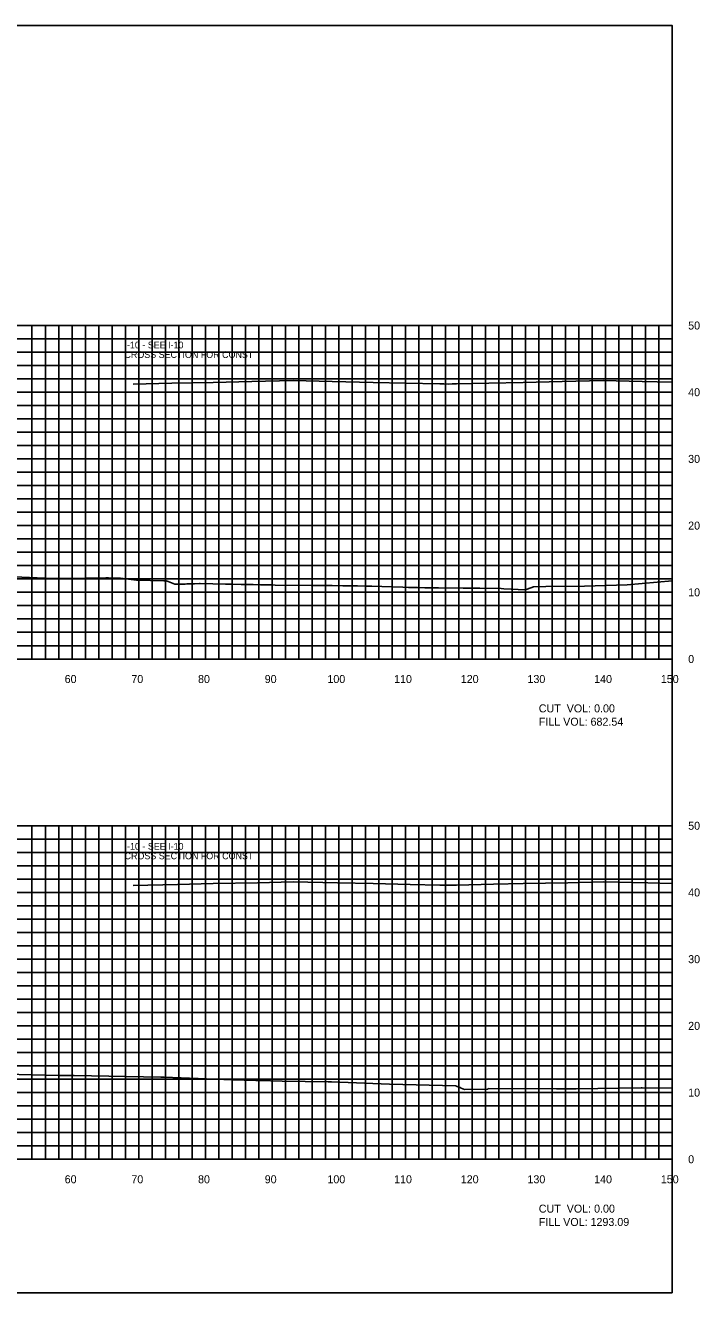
# Model space of a CAD drawing. Extents: x 1797714 to 1804825, y 249015 to 250269.
# Drawn here: x 1803024 to 1803125.1, y 250079.4 to 250269.4 of the extents above; entities that cross this region are included whole.
import ezdxf

# ---------------------------------------------------------------- set-up
doc = ezdxf.new("R2010")
doc.units = 0
for name, color, linetype in [('10', 7, 'Continuous'), ('3', 7, 'Continuous'), ('31', 7, 'Continuous'), ('60', 7, 'Continuous'), ('ANNO-TXT', 7, 'Continuous'), ('CL-CNST', 7, 'Continuous'), ('Level 62', 7, 'Continuous'), ('M-ROADS', 7, 'Continuous')]:
    doc.layers.add(name, color=color, linetype=linetype)

msp = doc.modelspace()

# ---------------------------------------------------------------- linework, layer by layer
msp.add_lwpolyline([(1802821, 250079.43), (1803121, 250079.43), (1803121, 250269.43), (1802821, 250269.43)], close=True)
at = {"layer": '60'}
for p, q in [((1803121, 250174.43), (1803121, 250224.43)), ((1803121.06, 250224.43), (1803121, 250224.43)), ((1803121.06, 250214.43), (1803121, 250214.43)), ((1803121.06, 250204.43), (1803121, 250204.43)), ((1803121.06, 250194.43), (1803121, 250194.43)), ((1803121.06, 250184.43), (1803121, 250184.43)), ((1802821, 250174.43), (1803121, 250174.43)), ((1803031, 250174.37), (1803031, 250174.43)), ((1803041, 250174.37), (1803041, 250174.43)), ((1803051, 250174.37), (1803051, 250174.43)), ((1803061, 250174.37), (1803061, 250174.43)), ((1803071, 250174.37), (1803071, 250174.43)), ((1803081, 250174.37), (1803081, 250174.43)), ((1803091, 250174.37), (1803091, 250174.43)), ((1803101, 250174.37), (1803101, 250174.43)), ((1803111, 250174.37), (1803111, 250174.43)), ((1803121, 250174.37), (1803121, 250174.43)), ((1803121.06, 250174.43), (1803121, 250174.43)), ((1803121, 250099.43), (1803121, 250149.43)), ((1803121.06, 250149.43), (1803121, 250149.43)), ((1803121.06, 250139.43), (1803121, 250139.43)), ((1803121.06, 250129.43), (1803121, 250129.43)), ((1803121.06, 250119.43), (1803121, 250119.43)), ((1803121.06, 250109.43), (1803121, 250109.43)), ((1802821, 250099.43), (1803121, 250099.43)), ((1803031, 250099.37), (1803031, 250099.43)), ((1803041, 250099.37), (1803041, 250099.43)), ((1803051, 250099.37), (1803051, 250099.43)), ((1803061, 250099.37), (1803061, 250099.43)), ((1803071, 250099.37), (1803071, 250099.43)), ((1803081, 250099.37), (1803081, 250099.43)), ((1803091, 250099.37), (1803091, 250099.43)), ((1803101, 250099.37), (1803101, 250099.43)), ((1803111, 250099.37), (1803111, 250099.43)), ((1803121, 250099.37), (1803121, 250099.43)), ((1803121.06, 250099.43), (1803121, 250099.43))]:
    msp.add_line(p, q, dxfattribs=at)
at = {"layer": 'CL-CNST'}
for points in [[(1803040.16, 250215.64), (1803045.99, 250215.77), (1803052.16, 250215.91), (1803057.99, 250216.04), (1803064.16, 250216.17), (1803069.99, 250216.04), (1803076.16, 250215.91), (1803081.02, 250215.8), (1803086.16, 250215.69), (1803086.77, 250215.68), (1803087.41, 250215.66), (1803087.41, 250215.66), (1803087.41, 250215.66), (1803088.02, 250215.67), (1803088.66, 250215.69), (1803093.52, 250215.8), (1803098.66, 250215.91), (1803104.5, 250216.04), (1803110.66, 250216.17), (1803116.5, 250216.04), (1803121, 250215.94)], [(1803040.17, 250140.48), (1803046.83, 250140.63), (1803052.17, 250140.75), (1803058.83, 250140.89), (1803064.17, 250141.01), (1803070.83, 250140.87), (1803076.17, 250140.75), (1803081.72, 250140.63), (1803086.17, 250140.53), (1803086.87, 250140.51), (1803087.42, 250140.5), (1803087.42, 250140.5), (1803087.42, 250140.5), (1803088.12, 250140.52), (1803088.67, 250140.53), (1803094.23, 250140.65), (1803098.67, 250140.75), (1803105.34, 250140.89), (1803110.67, 250141.01), (1803117.34, 250140.86), (1803121, 250140.78)]]:
    msp.add_lwpolyline(points, dxfattribs=at)
at = {"layer": 'Level 62'}
for p, q in [((1802821, 250224.43), (1803121, 250224.43)), ((1803025, 250174.43), (1803025, 250224.43)), ((1803027, 250174.43), (1803027, 250224.43)), ((1803029, 250174.43), (1803029, 250224.43)), ((1803031, 250174.43), (1803031, 250224.43)), ((1803033, 250174.43), (1803033, 250224.43)), ((1803035, 250174.43), (1803035, 250224.43)), ((1803037, 250174.43), (1803037, 250224.43)), ((1803039, 250174.43), (1803039, 250224.43)), ((1803041, 250174.43), (1803041, 250224.43)), ((1803043, 250174.43), (1803043, 250224.43)), ((1803045, 250174.43), (1803045, 250224.43)), ((1803047, 250174.43), (1803047, 250224.43)), ((1803049, 250174.43), (1803049, 250224.43)), ((1803051, 250174.43), (1803051, 250224.43)), ((1803053, 250174.43), (1803053, 250224.43)), ((1803055, 250174.43), (1803055, 250224.43)), ((1803057, 250174.43), (1803057, 250224.43)), ((1803059, 250174.43), (1803059, 250224.43)), ((1803061, 250174.43), (1803061, 250224.43)), ((1803063, 250174.43), (1803063, 250224.43)), ((1803065, 250174.43), (1803065, 250224.43)), ((1803067, 250174.43), (1803067, 250224.43)), ((1803069, 250174.43), (1803069, 250224.43)), ((1803071, 250174.43), (1803071, 250224.43)), ((1803073, 250174.43), (1803073, 250224.43)), ((1803075, 250174.43), (1803075, 250224.43)), ((1803077, 250174.43), (1803077, 250224.43)), ((1803079, 250174.43), (1803079, 250224.43)), ((1803081, 250174.43), (1803081, 250224.43)), ((1803083, 250174.43), (1803083, 250224.43)), ((1803085, 250174.43), (1803085, 250224.43)), ((1803087, 250174.43), (1803087, 250224.43)), ((1803089, 250174.43), (1803089, 250224.43)), ((1803091, 250174.43), (1803091, 250224.43)), ((1803093, 250174.43), (1803093, 250224.43)), ((1803095, 250174.43), (1803095, 250224.43)), ((1803097, 250174.43), (1803097, 250224.43)), ((1803099, 250174.43), (1803099, 250224.43)), ((1803101, 250174.43), (1803101, 250224.43)), ((1803103, 250174.43), (1803103, 250224.43)), ((1803105, 250174.43), (1803105, 250224.43)), ((1803107, 250174.43), (1803107, 250224.43)), ((1803109, 250174.43), (1803109, 250224.43)), ((1803111, 250174.43), (1803111, 250224.43)), ((1803113, 250174.43), (1803113, 250224.43)), ((1803115, 250174.43), (1803115, 250224.43)), ((1803117, 250174.43), (1803117, 250224.43)), ((1803119, 250174.43), (1803119, 250224.43)), ((1803121, 250174.43), (1803121, 250224.43)), ((1802821, 250222.43), (1803121, 250222.43)), ((1802821, 250220.43), (1803121, 250220.43)), ((1802821, 250218.43), (1803121, 250218.43)), ((1802821, 250216.43), (1803121, 250216.43)), ((1802821, 250214.43), (1803121, 250214.43)), ((1802821, 250212.43), (1803121, 250212.43)), ((1802821, 250210.43), (1803121, 250210.43)), ((1802821, 250208.43), (1803121, 250208.43)), ((1802821, 250206.43), (1803121, 250206.43)), ((1802821, 250204.43), (1803121, 250204.43)), ((1802821, 250202.43), (1803121, 250202.43)), ((1802821, 250200.43), (1803121, 250200.43)), ((1802821, 250198.43), (1803121, 250198.43)), ((1802821, 250196.43), (1803121, 250196.43)), ((1802821, 250194.43), (1803121, 250194.43)), ((1802821, 250192.43), (1803121, 250192.43)), ((1802821, 250190.43), (1803121, 250190.43)), ((1802821, 250188.43), (1803121, 250188.43)), ((1802821, 250186.43), (1803121, 250186.43)), ((1802821, 250184.43), (1803121, 250184.43)), ((1802821, 250182.43), (1803121, 250182.43)), ((1802821, 250180.43), (1803121, 250180.43)), ((1802821, 250178.43), (1803121, 250178.43)), ((1802821, 250176.43), (1803121, 250176.43)), ((1802821, 250174.43), (1803121, 250174.43)), ((1802821, 250149.43), (1803121, 250149.43)), ((1803025, 250099.43), (1803025, 250149.43)), ((1803027, 250099.43), (1803027, 250149.43)), ((1803029, 250099.43), (1803029, 250149.43)), ((1803031, 250099.43), (1803031, 250149.43)), ((1803033, 250099.43), (1803033, 250149.43)), ((1803035, 250099.43), (1803035, 250149.43)), ((1803037, 250099.43), (1803037, 250149.43)), ((1803039, 250099.43), (1803039, 250149.43)), ((1803041, 250099.43), (1803041, 250149.43)), ((1803043, 250099.43), (1803043, 250149.43)), ((1803045, 250099.43), (1803045, 250149.43)), ((1803047, 250099.43), (1803047, 250149.43)), ((1803049, 250099.43), (1803049, 250149.43)), ((1803051, 250099.43), (1803051, 250149.43)), ((1803053, 250099.43), (1803053, 250149.43)), ((1803055, 250099.43), (1803055, 250149.43)), ((1803057, 250099.43), (1803057, 250149.43)), ((1803059, 250099.43), (1803059, 250149.43)), ((1803061, 250099.43), (1803061, 250149.43)), ((1803063, 250099.43), (1803063, 250149.43)), ((1803065, 250099.43), (1803065, 250149.43)), ((1803067, 250099.43), (1803067, 250149.43)), ((1803069, 250099.43), (1803069, 250149.43)), ((1803071, 250099.43), (1803071, 250149.43)), ((1803073, 250099.43), (1803073, 250149.43)), ((1803075, 250099.43), (1803075, 250149.43)), ((1803077, 250099.43), (1803077, 250149.43)), ((1803079, 250099.43), (1803079, 250149.43)), ((1803081, 250099.43), (1803081, 250149.43)), ((1803083, 250099.43), (1803083, 250149.43)), ((1803085, 250099.43), (1803085, 250149.43)), ((1803087, 250099.43), (1803087, 250149.43)), ((1803089, 250099.43), (1803089, 250149.43)), ((1803091, 250099.43), (1803091, 250149.43)), ((1803093, 250099.43), (1803093, 250149.43)), ((1803095, 250099.43), (1803095, 250149.43)), ((1803097, 250099.43), (1803097, 250149.43)), ((1803099, 250099.43), (1803099, 250149.43)), ((1803101, 250099.43), (1803101, 250149.43)), ((1803103, 250099.43), (1803103, 250149.43)), ((1803105, 250099.43), (1803105, 250149.43)), ((1803107, 250099.43), (1803107, 250149.43)), ((1803109, 250099.43), (1803109, 250149.43)), ((1803111, 250099.43), (1803111, 250149.43)), ((1803113, 250099.43), (1803113, 250149.43)), ((1803115, 250099.43), (1803115, 250149.43)), ((1803117, 250099.43), (1803117, 250149.43)), ((1803119, 250099.43), (1803119, 250149.43)), ((1803121, 250099.43), (1803121, 250149.43)), ((1802821, 250147.43), (1803121, 250147.43)), ((1802821, 250145.43), (1803121, 250145.43)), ((1802821, 250143.43), (1803121, 250143.43)), ((1802821, 250141.43), (1803121, 250141.43)), ((1802821, 250139.43), (1803121, 250139.43)), ((1802821, 250137.43), (1803121, 250137.43)), ((1802821, 250135.43), (1803121, 250135.43)), ((1802821, 250133.43), (1803121, 250133.43)), ((1802821, 250131.43), (1803121, 250131.43)), ((1802821, 250129.43), (1803121, 250129.43)), ((1802821, 250127.43), (1803121, 250127.43)), ((1802821, 250125.43), (1803121, 250125.43)), ((1802821, 250123.43), (1803121, 250123.43)), ((1802821, 250121.43), (1803121, 250121.43)), ((1802821, 250119.43), (1803121, 250119.43)), ((1802821, 250117.43), (1803121, 250117.43)), ((1802821, 250115.43), (1803121, 250115.43)), ((1802821, 250113.43), (1803121, 250113.43)), ((1802821, 250111.43), (1803121, 250111.43)), ((1802821, 250109.43), (1803121, 250109.43)), ((1802821, 250107.43), (1803121, 250107.43)), ((1802821, 250105.43), (1803121, 250105.43)), ((1802821, 250103.43), (1803121, 250103.43)), ((1802821, 250101.43), (1803121, 250101.43)), ((1802821, 250099.43), (1803121, 250099.43))]:
    msp.add_line(p, q, dxfattribs=at)
at = {"layer": 'M-ROADS'}
for points in [[(1803014.19, 250187.11), (1803026.94, 250186.57), (1803029.16, 250186.48), (1803029.41, 250186.48), (1803029.42, 250186.48), (1803029.67, 250186.48), (1803030.26, 250186.48), (1803036.09, 250186.59), (1803036.48, 250186.59), (1803038.28, 250186.53), (1803040.65, 250186.26), (1803040.72, 250186.26), (1803044.75, 250186.16), (1803044.88, 250186.16), (1803045.08, 250186.15), (1803045.13, 250186.14), (1803045.28, 250186.11), (1803045.4, 250186.06), (1803046.41, 250185.64), (1803047.47, 250185.65), (1803047.56, 250185.66), (1803047.67, 250185.66), (1803047.81, 250185.66), (1803047.98, 250185.67), (1803048.2, 250185.68), (1803048.48, 250185.68), (1803048.86, 250185.7), (1803049.38, 250185.71), (1803050.1, 250185.73), (1803050.12, 250185.73), (1803050.16, 250185.73), (1803050.16, 250185.73), (1803050.22, 250185.73), (1803054, 250185.66), (1803054.9, 250185.64), (1803056.35, 250185.62), (1803056.67, 250185.61), (1803058.19, 250185.58), (1803059.26, 250185.56), (1803060.04, 250185.54), (1803060.35, 250185.54), (1803060.98, 250185.53), (1803061.48, 250185.52), (1803066.86, 250185.47), (1803068.72, 250185.45), (1803069.23, 250185.44), (1803069.64, 250185.44), (1803070.02, 250185.43), (1803071.61, 250185.41), (1803073.34, 250185.39), (1803073.79, 250185.38), (1803073.82, 250185.38), (1803075.12, 250185.36), (1803075.28, 250185.36), (1803075.98, 250185.33), (1803078.97, 250185.24), (1803080.59, 250185.18), (1803081.44, 250185.17), (1803082.8, 250185.13), (1803083.92, 250185.11), (1803085.98, 250185.09), (1803089.68, 250185.07), (1803092, 250185.03), (1803092.15, 250185.03), (1803095.36, 250185), (1803095.77, 250184.97), (1803099.01, 250184.79), (1803099.27, 250184.88), (1803100.2, 250185.27), (1803102.07, 250185.29), (1803107.84, 250185.35), (1803114.23, 250185.57), (1803121, 250186.13)], [(1803016.86, 250112.3), (1803029.15, 250112.01), (1803029.59, 250112), (1803030.06, 250112), (1803030.08, 250112), (1803030.57, 250111.99), (1803031.33, 250111.97), (1803044.33, 250111.74), (1803044.58, 250111.74), (1803044.83, 250111.74), (1803055.04, 250111.35), (1803058.56, 250111.24), (1803058.68, 250111.24), (1803059.05, 250111.25), (1803062.54, 250111.15), (1803069.41, 250111.06), (1803069.71, 250111.06), (1803069.91, 250111.06), (1803078.6, 250110.7), (1803088.58, 250110.42), (1803088.59, 250110.42), (1803088.61, 250110.41), (1803089.07, 250110.22), (1803089.21, 250110.17), (1803089.38, 250110.11), (1803089.87, 250109.9), (1803093.26, 250109.95), (1803093.36, 250109.96), (1803093.46, 250110.02), (1803103.68, 250109.99), (1803104.01, 250109.98), (1803106.59, 250110), (1803116.36, 250110.13), (1803116.52, 250110.13), (1803121, 250110.08)]]:
    msp.add_lwpolyline(points, dxfattribs=at)

# ---------------------------------------------------------------- texts
at = {"layer": '10'}
for s, p in [('60', (1803029.9, 250170.83)), ('70', (1803039.9, 250170.83)), ('80', (1803049.9, 250170.83)), ('90', (1803059.9, 250170.83)), ('100', (1803069.3, 250170.83)), ('110', (1803079.3, 250170.83)), ('120', (1803089.3, 250170.83)), ('130', (1803099.3, 250170.83)), ('140', (1803109.3, 250170.83)), ('150', (1803119.3, 250170.83)), ('60', (1803029.9, 250095.83)), ('70', (1803039.9, 250095.83)), ('80', (1803049.9, 250095.83)), ('90', (1803059.9, 250095.83)), ('100', (1803069.3, 250095.83)), ('110', (1803079.3, 250095.83)), ('120', (1803089.3, 250095.83)), ('130', (1803099.3, 250095.83)), ('140', (1803109.3, 250095.83)), ('150', (1803119.3, 250095.83))]:
    msp.add_text(s, height=1.2, dxfattribs=at).set_placement(p)
at = {"layer": '3'}
for s, p in [('CROSS SECTION FOR CONST ', (1803038.87, 250219.57)), ('I-10 - SEE I-10 ', (1803038.87, 250221.01)), ('I-10 - SEE I-10 ', (1803038.88, 250145.85)), ('CROSS SECTION FOR CONST ', (1803038.88, 250144.41))]:
    msp.add_text(s, height=1, dxfattribs=at).set_placement(p)
at = {"layer": '31'}
for s, p in [('50', (1803123.4, 250223.83)), ('40', (1803123.4, 250213.83)), ('30', (1803123.4, 250203.83)), ('20', (1803123.4, 250193.83)), ('10', (1803123.4, 250183.83)), ('0', (1803123.4, 250173.83)), ('50', (1803123.4, 250148.83)), ('40', (1803123.4, 250138.83)), ('30', (1803123.4, 250128.83)), ('20', (1803123.4, 250118.83)), ('10', (1803123.4, 250108.83)), ('0', (1803123.4, 250098.83))]:
    msp.add_text(s, height=1.2, dxfattribs=at).set_placement(p)
at = {"layer": 'ANNO-TXT'}
for s, p in [('CUT  VOL: 0.00', (1803101, 250166.43)), ('FILL VOL: 682.54', (1803101, 250164.43)), ('CUT  VOL: 0.00', (1803101, 250091.43)), ('FILL VOL: 1293.09', (1803101, 250089.43))]:
    msp.add_text(s, height=1.2, dxfattribs=at).set_placement(p)

doc.saveas('drawing.dxf')
